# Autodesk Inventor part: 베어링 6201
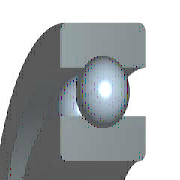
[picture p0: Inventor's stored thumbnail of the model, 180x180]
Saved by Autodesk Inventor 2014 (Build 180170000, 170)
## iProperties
Created: 2015-12
Part Number: 베어링 6201
Material: 강철, 연강
Description: 깊은 그루브 볼 베어링
Document SubType Name: Modeling
Standard: KS B 2023
Designer: mdu
Standards Organization: KS
Language: ko-KR
Size Designation: 6201 - 12 x 32 x 10
Categories: <MemberInstance><Categories><Category DisplayName="샤프트 부품" InternalName="7f7aeb1f-a693-4053-b835-cee3144e0d98" Mnemonic="SHFT"><Category DisplayName="베어링" Inter
Density: 7.86 g/cm^3
Mass: 32.7519 g
Surface Area: 42.5728 cm^2
Volume: 4.16691 cm^3
Appearance: 밝은 황색
Company: 한국ATC센터
IsCustomPart: 1
Author: mdu
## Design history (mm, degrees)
sketch "스케치" dims "d0" = 5.2 (= -0.26 x WD + 0.26 x BD)
  geometry: L1 (2.4, 11)-(7.6, 11); L2 (5, 11)-(5, 8.4); L3 (5, 11)-(5, 13.6); L4 (3.068, 9.26)-(0, 9.26); L5 (0, 6)-(10, 6); L6 (3.068, 12.74)-(0, 12.74); L7 (0, 16)-(10, 16); L8 (10, 6)-(10, 9.26); L9 (6.932, 9.26)-(10, 9.26); L10 (6.932, 12.74)-(10, 12.74); L11 (10, 16)-(10, 12.74); L12 (-1.4, 0)-(8.4, 0) reference; L13 (0, -0.3)-(0, 5.3) reference
  constraints: 22 end point, 4 point on line, 2 collinear, 2 perpendicular, 2 symmetric about line, 1 midpoint, 1 parallel, 14 other
  dimensions: "d9" = 12 diameter of L5 L12 (= WD); "d11" = 32 diameter of L7 L12 (= BD); "d12" = 10 distance between parallel lines of L8 L13 (= KB); "d13" = 18.52 diameter of L9 L12 (= 0.326 x BD + 0.674 x WD)
revolve "본체" stored, may be unused: angle "d6" = 90 deg
revolve "볼" stored, may be unused: angle "d7" = 90 deg
pattern_circular "IDS_ARRAYBALL[SIMPL:T]" dims angle "d3" = 360 deg
body "Solid1"
fillet "모깎기1" dims "d1" = 0.6 (= KRS)
other parameters: "WD" = 12 [user parameter; used in 5 equation terms], "BD" = 32 [user parameter; used in 5 equation terms], "KB" = 10 [user parameter; used in 1 equation term], "KRS" = 0.6 [user parameter; used in 1 equation term], "d4" = 0, "d5" = 0, "d8" = 0, "d14" = 0, "d15" = 0, "BBA" = 0 [user parameter], "BC0" = 3100000 [user parameter], "BC" = 6890000 [user parameter], "BR" = 16 (= 0.5 x BD) [user parameter], "WR" = 6 (= 0.5 x WD) [user parameter]
